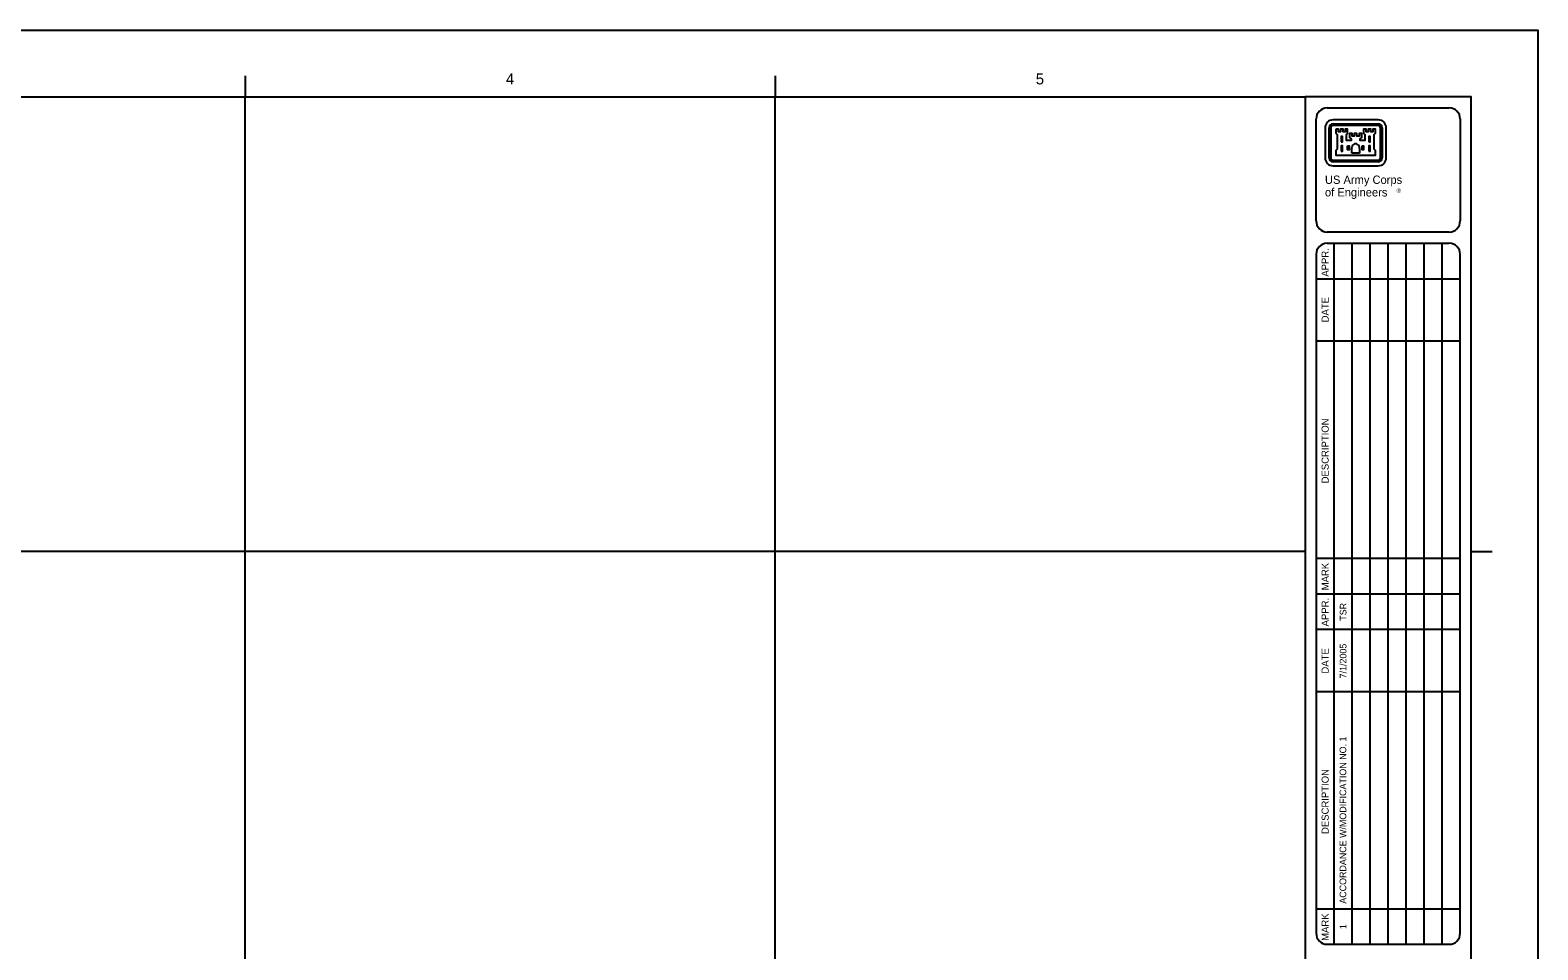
# Model space of a CAD drawing. Extents: x 0 to 2.83, y 0 to 1.83.
# Drawn here: x 1.417 to 2.833, y 0.97 to 1.833 of the extents above; entities that cross this region are included whole.
import ezdxf

# ---------------------------------------------------------------- set-up
doc = ezdxf.new("R2010")
doc.units = 0
for name, color, linetype in [('G-ANNO-SYMB', 7, 'Continuous'), ('G-ANNO-TEXT', 7, 'Continuous'), ('G-ANNO-TEXT-SAMP', 7, 'Continuous'), ('G-ANNO-TTLB', 7, 'Continuous'), ('G-ANNO-TTLB-GRID', 7, 'Continuous')]:
    doc.layers.add(name, color=color, linetype=linetype)

msp = doc.modelspace()

# ---------------------------------------------------------------- linework, layer by layer
at = {"layer": 'G-ANNO-SYMB'}
for p, q in [((2.6834, 1.7491), (2.6409, 1.7491)), ((2.6409, 1.7491), (2.6409, 1.7491)), ((2.6409, 1.7454), (2.6834, 1.7454)), ((2.6834, 1.7437), (2.6409, 1.7437)), ((2.6834, 1.7437), (2.6834, 1.7437)), ((2.6334, 1.7416), (2.6334, 1.7135)), ((2.6372, 1.7135), (2.6372, 1.7416)), ((2.6372, 1.7416), (2.6372, 1.7416)), ((2.6388, 1.7416), (2.6388, 1.7135)), ((2.6855, 1.7135), (2.6855, 1.7416)), ((2.6871, 1.7416), (2.6871, 1.7135)), ((2.6908, 1.7135), (2.6908, 1.7416)), ((2.6584, 1.7179), (2.6584, 1.7221)), ((2.6659, 1.7179), (2.6584, 1.7179)), ((2.6659, 1.7221), (2.6659, 1.7179)), ((2.6409, 1.7114), (2.6834, 1.7114)), ((2.6834, 1.7098), (2.6409, 1.7098)), ((2.6409, 1.706), (2.6834, 1.706))]:
    msp.add_line(p, q, dxfattribs=at)
for points in [[(2.6434, 1.7404), (2.6434, 1.7366), (2.6447, 1.7354), (2.6447, 1.7216), (2.6434, 1.7204), (2.6434, 1.716), (2.6809, 1.716), (2.6809, 1.7204), (2.6796, 1.7216), (2.6796, 1.7354), (2.6809, 1.7366), (2.6809, 1.7404), (2.6784, 1.7404), (2.6784, 1.7379), (2.6765, 1.7379), (2.6765, 1.7404), (2.674, 1.7404), (2.674, 1.7379), (2.6721, 1.7379), (2.6721, 1.7404), (2.6696, 1.7404), (2.6696, 1.7366), (2.6709, 1.7354), (2.6709, 1.7298), (2.6665, 1.7298), (2.6665, 1.7313), (2.6678, 1.7326), (2.6678, 1.7363), (2.6653, 1.7363), (2.6653, 1.7338), (2.6634, 1.7338), (2.6634, 1.7363), (2.6609, 1.7363), (2.6609, 1.7338), (2.659, 1.7338), (2.659, 1.7363), (2.6565, 1.7363), (2.6565, 1.7326), (2.6578, 1.7313), (2.6578, 1.7298), (2.6534, 1.7298), (2.6534, 1.7354), (2.6546, 1.7366), (2.6546, 1.7404), (2.6522, 1.7404), (2.6522, 1.7379), (2.6503, 1.7379), (2.6503, 1.7404), (2.6478, 1.7404), (2.6478, 1.7379), (2.6459, 1.7379), (2.6459, 1.7404), (2.6434, 1.7404)], [(2.6484, 1.7285), (2.6497, 1.7285), (2.6497, 1.7335), (2.6484, 1.7335), (2.6484, 1.7285)], [(2.6746, 1.7335), (2.6747, 1.7335)], [(2.6746, 1.7285), (2.6759, 1.7285), (2.6759, 1.7335), (2.6746, 1.7335), (2.6746, 1.7285)], [(2.6758, 1.7285), (2.6759, 1.7286)], [(2.6484, 1.7198), (2.6497, 1.7198), (2.6497, 1.7248), (2.6484, 1.7248), (2.6484, 1.7198)], [(2.6546, 1.7248), (2.6559, 1.7248), (2.6559, 1.721), (2.6546, 1.721), (2.6546, 1.7248)], [(2.6684, 1.7248), (2.6696, 1.7248), (2.6696, 1.721), (2.6684, 1.721), (2.6684, 1.7248)], [(2.6746, 1.7198), (2.6759, 1.7198), (2.6759, 1.7248), (2.6746, 1.7248), (2.6746, 1.7198)]]:
    msp.add_lwpolyline(points, dxfattribs=at)
for centre, radius, start, end in [((2.6409, 1.7416), 0.00749, 90, 180), ((2.6409, 1.7416), 0.00375, 90, 180), ((2.6409, 1.7416), 0.0021, 90, 180), ((2.6834, 1.7416), 0.00749, 0, 90), ((2.6834, 1.7416), 0.00375, 0, 90), ((2.6834, 1.7416), 0.0021, 0, 90), ((2.6409, 1.7135), 0.00749, 180, 270), ((2.6409, 1.7135), 0.00375, 180, 270), ((2.6409, 1.7135), 0.0021, 180, 270), ((2.6834, 1.7135), 0.00749, 270, 360), ((2.6834, 1.7135), 0.00375, 270, 360), ((2.6834, 1.7135), 0.0021, 270, 360)]:
    msp.add_arc(centre, radius, start, end, dxfattribs=at)
msp.add_ellipse((2.6621, 1.7221), major_axis=(0, 0.00452), ratio=0.827815, start_param=4.712389, end_param=7.853982, dxfattribs=at)
at = {"layer": 'G-ANNO-TEXT'}
msp.add_line((2.7708, 1.3438), (2.7905, 1.3438), dxfattribs=at)
at = {"layer": 'G-ANNO-TTLB'}
for p, q in [((1.6188, 1.7905), (1.6188, 1.7708)), ((2.1167, 1.7905), (2.1167, 1.7708)), ((2.6354, 1.6333), (2.75, 1.6333)), ((2.6419, 1.6), (2.6419, 1.6333)), ((2.6419, 1.6), (2.6419, 1.6333)), ((2.6589, 1.6), (2.6589, 1.6333)), ((2.6758, 1.6), (2.6758, 1.6333)), ((2.6927, 1.6), (2.6927, 1.6333)), ((2.7096, 1.6), (2.7096, 1.6333)), ((2.7266, 1.6), (2.7266, 1.6333)), ((2.7435, 1.6), (2.7435, 1.6333)), ((2.625, 1.6), (2.6419, 1.6)), ((2.6419, 1.6), (2.6589, 1.6)), ((2.6419, 1.5417), (2.6419, 1.6)), ((2.6589, 1.6), (2.6758, 1.6)), ((2.6589, 1.5417), (2.6589, 1.6)), ((2.6758, 1.6), (2.6927, 1.6)), ((2.6758, 1.5417), (2.6758, 1.6)), ((2.6927, 1.6), (2.7096, 1.6)), ((2.6927, 1.5417), (2.6927, 1.6)), ((2.7096, 1.6), (2.7266, 1.6)), ((2.7096, 1.5417), (2.7096, 1.6)), ((2.7266, 1.6), (2.7435, 1.6)), ((2.7266, 1.5417), (2.7266, 1.6)), ((2.7435, 1.6), (2.7604, 1.6)), ((2.7435, 1.5417), (2.7435, 1.6)), ((2.625, 1.5417), (2.6419, 1.5417)), ((2.6419, 1.3375), (2.6419, 1.5417)), ((2.6419, 1.5417), (2.6589, 1.5417)), ((2.6589, 1.3375), (2.6589, 1.5417)), ((2.6589, 1.5417), (2.6758, 1.5417)), ((2.6758, 1.3375), (2.6758, 1.5417)), ((2.6758, 1.5417), (2.6927, 1.5417)), ((2.6927, 1.3375), (2.6927, 1.5417)), ((2.6927, 1.5417), (2.7096, 1.5417)), ((2.7096, 1.3375), (2.7096, 1.5417)), ((2.7096, 1.5417), (2.7266, 1.5417)), ((2.7266, 1.3375), (2.7266, 1.5417)), ((2.7266, 1.5417), (2.7435, 1.5417)), ((2.7435, 1.3375), (2.7435, 1.5417)), ((2.7435, 1.5417), (2.7604, 1.5417)), ((2.625, 1.3375), (2.6419, 1.3375)), ((2.6419, 1.3042), (2.6419, 1.3375)), ((2.6419, 1.3375), (2.6589, 1.3375)), ((2.6589, 1.3042), (2.6589, 1.3375)), ((2.6589, 1.3375), (2.6758, 1.3375)), ((2.6758, 1.3042), (2.6758, 1.3375)), ((2.6758, 1.3375), (2.6927, 1.3375)), ((2.6927, 1.3042), (2.6927, 1.3375)), ((2.6927, 1.3375), (2.7096, 1.3375)), ((2.7096, 1.3042), (2.7096, 1.3375)), ((2.7096, 1.3375), (2.7266, 1.3375)), ((2.7266, 1.3375), (2.7435, 1.3375)), ((2.7266, 1.3042), (2.7266, 1.3375)), ((2.7435, 1.3042), (2.7435, 1.3375)), ((2.7435, 1.3375), (2.7604, 1.3375)), ((2.625, 1.3042), (2.7604, 1.3042)), ((2.6419, 1.2708), (2.6419, 1.3042)), ((2.6419, 1.2708), (2.6419, 1.3042)), ((2.6589, 1.2708), (2.6589, 1.3042)), ((2.6758, 1.2708), (2.6758, 1.3042)), ((2.6927, 1.2708), (2.6927, 1.3042)), ((2.7096, 1.2708), (2.7096, 1.3042)), ((2.7266, 1.2708), (2.7266, 1.3042)), ((2.7435, 1.2708), (2.7435, 1.3042)), ((2.625, 1.2708), (2.6419, 1.2708)), ((2.6419, 1.2125), (2.6419, 1.2708)), ((2.6419, 1.2708), (2.6589, 1.2708)), ((2.6589, 1.2125), (2.6589, 1.2708)), ((2.6589, 1.2708), (2.6758, 1.2708)), ((2.6758, 1.2125), (2.6758, 1.2708)), ((2.6758, 1.2708), (2.6927, 1.2708)), ((2.6927, 1.2125), (2.6927, 1.2708)), ((2.6927, 1.2708), (2.7096, 1.2708)), ((2.7096, 1.2125), (2.7096, 1.2708)), ((2.7096, 1.2708), (2.7266, 1.2708)), ((2.7266, 1.2125), (2.7266, 1.2708)), ((2.7266, 1.2708), (2.7435, 1.2708)), ((2.7435, 1.2708), (2.7604, 1.2708)), ((2.7435, 1.2125), (2.7435, 1.2708)), ((2.625, 1.2125), (2.6419, 1.2125)), ((2.6419, 1.0083), (2.6419, 1.2125)), ((2.6419, 1.2125), (2.6589, 1.2125)), ((2.6589, 1.0083), (2.6589, 1.2125)), ((2.6589, 1.2125), (2.6758, 1.2125)), ((2.6758, 1.0083), (2.6758, 1.2125)), ((2.6758, 1.2125), (2.6927, 1.2125)), ((2.6927, 1.0083), (2.6927, 1.2125)), ((2.6927, 1.2125), (2.7096, 1.2125)), ((2.7096, 1.0083), (2.7096, 1.2125)), ((2.7096, 1.2125), (2.7266, 1.2125)), ((2.7266, 1.0083), (2.7266, 1.2125)), ((2.7266, 1.2125), (2.7435, 1.2125)), ((2.7435, 1.2125), (2.7604, 1.2125)), ((2.7435, 1.0083), (2.7435, 1.2125)), ((2.625, 1.0083), (2.6419, 1.0083)), ((2.6419, 0.975), (2.6419, 1.0083)), ((2.6419, 1.0083), (2.6589, 1.0083)), ((2.6589, 0.975), (2.6589, 1.0083)), ((2.6589, 1.0083), (2.6758, 1.0083)), ((2.6758, 0.975), (2.6758, 1.0083)), ((2.6758, 1.0083), (2.6927, 1.0083)), ((2.6927, 0.975), (2.6927, 1.0083)), ((2.6927, 1.0083), (2.7096, 1.0083)), ((2.7096, 0.975), (2.7096, 1.0083)), ((2.7096, 1.0083), (2.7266, 1.0083)), ((2.7266, 0.975), (2.7266, 1.0083)), ((2.7266, 1.0083), (2.7435, 1.0083)), ((2.7435, 1.0083), (2.7604, 1.0083)), ((2.7435, 0.975), (2.7435, 1.0083)), ((2.6354, 0.975), (2.75, 0.975))]:
    msp.add_line(p, q, dxfattribs=at)
for points in [[(0, 1.8333), (2.8333, 1.8333), (2.8333, 0), (0, 0)], [(0.125, 1.7708), (2.6146, 1.7708), (2.6146, 0.0625), (0.125, 0.0625)], [(2.6146, 0.0625), (2.7708, 0.0625), (2.7708, 1.7708), (2.6146, 1.7708)]]:
    msp.add_lwpolyline(points, close=True, dxfattribs=at)
for points in [[(2.6354, 1.7604), (2.75, 1.7604)], [(2.625, 1.6542), (2.625, 1.75)], [(2.7604, 1.75), (2.7604, 1.6542)], [(2.75, 1.6438), (2.6354, 1.6438)], [(2.625, 1.6229), (2.625, 0.9854)], [(2.7604, 0.9854), (2.7604, 1.6229)]]:
    msp.add_lwpolyline(points, dxfattribs=at)
for centre, start, end in [((2.6354, 1.75), 90, 180), ((2.75, 1.75), 0, 90), ((2.6354, 1.6542), 180, 270), ((2.75, 1.6542), 270, 0), ((2.6354, 1.6229), 90, 180), ((2.75, 1.6229), 0, 90), ((2.6354, 0.9854), 180, 270), ((2.75, 0.9854), 270, 0)]:
    msp.add_arc(centre, 0.0104, start, end, dxfattribs=at)
at = {"layer": 'G-ANNO-TTLB-GRID'}
for p, q in [((1.6188, 0.0625), (1.6188, 1.7708)), ((2.1167, 0.0625), (2.1167, 1.7708)), ((2.6146, 1.3438), (0.125, 1.3438))]:
    msp.add_line(p, q, dxfattribs=at)

# ---------------------------------------------------------------- texts
at = {"layer": 'G-ANNO-SYMB'}
for s, height, p in [('US Army Corps', 0.007812, (2.6333, 1.689)), ('US Army Corps', 0.007812, (2.6333, 1.689)), ('of Engineers', 0.007812, (2.6333, 1.6772)), ('of Engineers', 0.007812, (2.6333, 1.6772)), ('®', 0.00417, (2.7006, 1.6806))]:
    msp.add_text(s, height=height, dxfattribs=at).set_placement(p)
at = {"layer": 'G-ANNO-TEXT'}
for s, p in [('4', (1.8637, 1.7824)), ('5', (2.3616, 1.7824))]:
    msp.add_text(s, height=0.0104, dxfattribs=at).set_placement(p)
for s, height, p in [('APPR.', 0.00667, (2.6368, 1.6019)), ('DATE', 0.00667, (2.6368, 1.559)), ('DESCRIPTION', 0.006667, (2.6368, 1.4078)), ('MARK', 0.00667, (2.6368, 1.3074)), ('APPR.', 0.00667, (2.6368, 1.2735)), ('DATE', 0.00667, (2.6368, 1.2292)), ('DESCRIPTION', 0.006667, (2.6368, 1.0786)), ('MARK', 0.00667, (2.6368, 0.9782))]:
    msp.add_text(s, height=height, rotation=90, dxfattribs=at).set_placement(p)
at = {"layer": 'G-ANNO-TEXT-SAMP'}
for s, p in [('TSR', (2.6535, 1.2788)), ('7/1/2005', (2.6535, 1.2247)), ('ACCORDANCE W/MODIFICATION NO. 1', (2.6533, 1.0131)), ('1', (2.6535, 0.9892))]:
    msp.add_text(s, height=0.00625, rotation=90, dxfattribs=at).set_placement(p)

doc.saveas('drawing.dxf')
